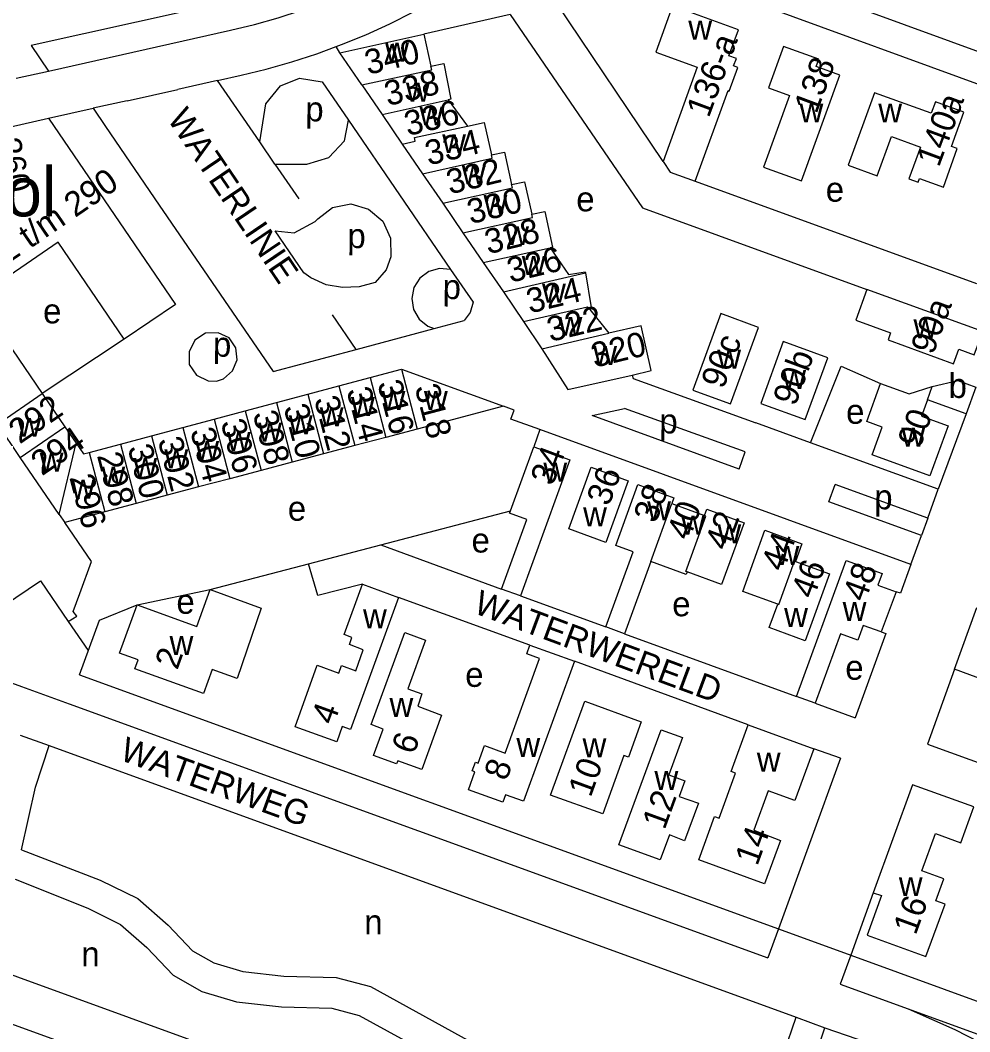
# Model space of a CAD drawing. Extents: x 154320 to 156262, y 382651 to 384180.
# Drawn here: x 155853.4 to 156007.7, y 383033.1 to 383197.4 of the extents above; entities that cross this region are included whole.
import ezdxf

# ---------------------------------------------------------------- set-up
doc = ezdxf.new("R2010")
doc.units = 0
for name, color, linetype in [('BLT_Basislijn', 7, 'Continuous'), ('BLT_Bebouwing', 7, 'Continuous'), ('BLT_Bebouwing_beschrifting', 7, 'Continuous'), ('BLT_Centroide', 7, 'Continuous'), ('BLT_Huisnummer', 7, 'Continuous'), ('BLT_Huisnummer_ tussenligend', 7, 'Continuous'), ('BLT_Huisnummer_reeks', 7, 'Continuous'), ('BLT_Onderverdeling_panden', 7, 'Continuous'), ('BLT_Straatnaam', 7, 'Continuous'), ('BLT_Vlakafsluiter', 7, 'Continuous')]:
    doc.layers.add(name, color=color, linetype=linetype)

msp = doc.modelspace()

# ---------------------------------------------------------------- linework, layer by layer
at = {"layer": 'BLT_Basislijn'}
for p, q in [((155957.88, 383174.46), (155940.61, 383200.09)), ((155933.05, 383198.35), (155919, 383195.11)), ((155855.18, 383193.28), (155858, 383189.14)), ((155905.36, 383192.11), (155904.75, 383193.12)), ((155852.75, 383187.97), (155858, 383189.14)), ((155885.5, 383187.62), (155879.03, 383186.17)), ((155892.33, 383177.64), (155885.5, 383187.62)), ((155870.79, 383184.33), (155865.29, 383183.1)), ((155858.01, 383181.48), (155865.29, 383183.1)), ((155906.77, 383181.19), (155923.36, 383156.92)), ((155894.82, 383174.02), (155892.33, 383177.64)), ((155894.82, 383174.02), (155898.67, 383168.4)), ((155963.09, 383171.24), (156008.81, 383154.64)), ((155899.5, 383156.39), (155894.84, 383163.18)), ((155908.03, 383143.95), (155904.17, 383149.58)), ((155920.68, 383147.32), (155925.56, 383148.62)), ((155908.03, 383143.95), (155920.68, 383147.32)), ((155870.34, 383145.59), (155856.99, 383136.76)), ((155894.54, 383140.36), (155908.03, 383143.95)), ((155946.33, 383133.19), (155951.61, 383134.37)), ((155970.25, 383124.49), (155946.33, 383133.19)), ((155971.22, 383127.33), (155951.61, 383134.37)), ((156007.09, 383133.49), (156002.58, 383121.25)), ((156002.58, 383121.25), (155981.83, 383128.76)), ((155970.25, 383124.49), (155971.22, 383127.33)), ((155984.81, 383119.19), (155985.83, 383122.01)), ((156000.87, 383116.55), (155985.83, 383122.01)), ((156000.87, 383116.55), (156002.58, 383121.25)), ((155999.84, 383113.73), (155984.81, 383119.19)), ((155912.02, 383112.19), (155933.06, 383117.7)), ((156000.87, 383116.55), (155999.84, 383113.73)), ((155998.13, 383109.03), (155999.84, 383113.73)), ((155900.28, 383109.12), (155912.02, 383112.19)), ((155884.29, 383104.93), (155900.28, 383109.12)), ((155872.41, 383102.46), (155884.29, 383104.93)), ((155866.29, 383099.97), (155872.41, 383102.46)), ((155863.08, 383091.1), (155866.29, 383099.97)), ((155861.19, 383099.73), (155864.46, 383095.07)), ((156005.23, 383092.02), (156000.83, 383079.85)), ((155853.42, 383081.31), (155858.12, 383079.6)), ((155858.12, 383079.6), (155979.47, 383035.48)), ((156000.83, 383079.85), (156058.97, 383058.73)), ((155986.69, 383077.55), (155976.61, 383049.82)), ((155992.01, 383055.71), (155988.35, 383045.55)), ((155976.61, 383049.82), (155974.9, 383045.12)), ((155988.35, 383045.55), (155986.65, 383040.85)), ((155979.47, 383035.48), (155984.17, 383033.77))]:
    msp.add_line(p, q, dxfattribs=at)
for points in [[(155932.23, 383223.07), (155925.3, 383217.82), (155914.61, 383210.57), (155899.48, 383204.01), (155880.87, 383198.99), (155855.18, 383193.28)], [(155858, 383189.14), (155887.6, 383195.77), (155891.49, 383196.72), (155895.34, 383197.79), (155899.14, 383199.05), (155902.9, 383200.42), (155906.6, 383201.93), (155910.24, 383203.58), (155913.82, 383205.38), (155918.19, 383207.8), (155924.24, 383211.67), (155929.2, 383214.78)], [(155960.94, 383209.9), (156026.16, 383186.09), (156037.02, 383182.14)], [(156024.45, 383181.39), (155960.61, 383204.7), (155940.61, 383200.09)], [(155904.75, 383193.12), (155905.6, 383193.43), (155909.56, 383195.04), (155913.48, 383196.81), (155917.32, 383198.74), (155920.78, 383200.65)], [(155933.05, 383198.35), (155954.54, 383166.91), (155990.99, 383153.67)], [(155885.5, 383187.62), (155889.31, 383188.47), (155893.38, 383189.46), (155897.53, 383190.62), (155901.61, 383191.96), (155904.75, 383193.12)], [(155892.33, 383177.64), (155893.32, 383183.84), (155895.69, 383186.77), (155898.79, 383187.99), (155902.51, 383187.42), (155906.77, 383181.19)], [(155865.29, 383183.1), (155867.28, 383180.15), (155876.02, 383167.37), (155894.54, 383140.36)], [(155894.82, 383174.02), (155899.97, 383174.02), (155903.57, 383175.08), (155906.09, 383177.8), (155906.77, 383181.19)], [(155894.84, 383163.18), (155897.91, 383162.86), (155901.36, 383164.69), (155901.78, 383165.15), (155904.18, 383166.99), (155907.14, 383167.59), (155910.03, 383166.71), (155912.32, 383164.74), (155913.58, 383162), (155913.66, 383158.98), (155912.87, 383156.86), (155911.1, 383154.81), (155908.49, 383154.09), (155905.78, 383154), (155903.11, 383154.45), (155900.65, 383155.59), (155899.5, 383156.39)], [(155923.36, 383156.92), (155921.56, 383157.09), (155919.82, 383156.59), (155918.37, 383155.51), (155917.35, 383154.01), (155917.07, 383152.22), (155917.34, 383150.43), (155918.24, 383148.86), (155919.65, 383147.73), (155920.68, 383147.32)], [(155923.36, 383156.92), (155926.99, 383151.61), (155926.54, 383149.92), (155925.56, 383148.62)], [(155981.83, 383128.76), (155986.78, 383141.2), (155993.22, 383138.43)], [(155952.86, 383139.78), (155952.99, 383139.19), (155972.93, 383132.03)], [(155937.87, 383130.94), (155933.15, 383132.6), (155933.69, 383134.08), (155931.93, 383134.71)], [(155981.83, 383128.76), (155972.93, 383132.03)], [(155937.87, 383130.94), (155936.86, 383128.14)], [(155998.13, 383109.03), (155937.87, 383130.94)], [(155912.02, 383112.19), (155931.64, 383105.01)], [(155909.06, 383105.8), (155901.79, 383103.97), (155900.28, 383109.12)], [(155998.13, 383109.03), (155996.43, 383104.33), (155995.74, 383104.58)], [(155936.22, 383095.93), (155914.89, 383103.67)], [(155934.69, 383103.9), (155948.55, 383098.88)], [(155830.73, 383097.54), (155853.63, 383089.22)], [(155951.61, 383097.77), (155979.55, 383087.59)], [(155993.32, 383098.05), (155994.05, 383097.79), (155989.08, 383084.12)], [(155971.69, 383082.98), (155943.47, 383093.29)], [(155863.08, 383091.1), (155976.61, 383049.82)], [(155853.63, 383089.22), (155861.38, 383086.4)], [(155861.38, 383086.4), (155974.9, 383045.12)], [(155982.59, 383086.48), (155989.08, 383084.12)], [(155853.65, 383062.66), (155855.93, 383072.86), (155858.12, 383079.6)], [(155986.69, 383077.55), (155982.37, 383079.1)], [(155853.65, 383062.66), (155866.44, 383057.77), (155872.53, 383054.76), (155877.48, 383050.43), (155881.4, 383046.27), (155884.9, 383044.3), (155889.57, 383042.9), (155896.23, 383042.16), (155904.77, 383041.94), (155910.34, 383040.46), (155932.43, 383028.32)], [(155852.58, 383057.9), (155864.43, 383053.19), (155869.73, 383050.56), (155874.01, 383046.82), (155878.28, 383042.3), (155882.92, 383039.67), (155888.57, 383037.98), (155895.89, 383037.17), (155904.05, 383036.95), (155908.47, 383035.79), (155926.08, 383026.11), (155919.49, 383022.53), (155917.44, 383018.56)], [(155903.98, 383015.47), (155817.04, 383047.08)], [(155917.44, 383018.56), (155843.64, 383045.39)], [(155988.35, 383045.55), (156070.59, 383015.65)], [(155986.65, 383040.85), (155997.68, 383036.84)], [(155997.68, 383036.84), (156068.88, 383010.95)], [(155997.68, 383036.84), (156005.3, 383033.52), (156013.2, 383029.41), (156022.56, 383023.53), (156030.91, 383017.21), (156037.92, 383011.01), (156044.25, 383004.31), (156050.51, 382996.85), (156052.83, 382993.58)], [(155932.43, 383028.32), (155941.43, 383024.01), (155958.17, 383023.07), (155962.36, 383025.98), (155967.49, 383028.21), (155972.18, 383028.67), (155975.7, 383027.95), (155976.87, 383028.3), (155977.49, 383029.67), (155979.47, 383035.48)], [(155962.2, 383019.78), (155964.8, 383021.59), (155968.76, 383023.31), (155971.92, 383023.62), (155975.94, 383022.79), (155980.5, 383024.18), (155982.14, 383027.83), (155984.17, 383033.77)], [(155984.17, 383033.77), (155992.84, 383030.77), (156002.07, 383026.75), (156009.47, 383022.9), (156018.29, 383017.36), (156026.15, 383011.4), (156032.7, 383005.62), (156038.64, 382999.33), (156044.57, 382992.26), (156045.87, 382990.43)]]:
    msp.add_lwpolyline(points, dxfattribs=at)
msp.add_lwpolyline([(155886.44, 383139.16), (155887.91, 383140.45), (155888.67, 383142.25), (155888.48, 383144.2), (155887.36, 383145.8), (155885.6, 383146.65), (155883.52, 383146.57), (155881.79, 383145.42), (155880.85, 383143.56), (155880.89, 383141.48), (155882.07, 383139.77), (155883.94, 383138.86), (155885.29, 383138.8)], close=True, dxfattribs=at)
at = {"layer": 'BLT_Bebouwing'}
for p, q in [((155905.36, 383192.11), (155919, 383195.11)), ((155919, 383195.11), (155920.15, 383189.92)), ((155963.42, 383189.75), (155957.88, 383174.46)), ((155908.93, 383186.89), (155912.21, 383182.09)), ((155922.98, 383184.48), (155926.1, 383180.19)), ((155912.21, 383182.09), (155915.5, 383177.29)), ((155821.39, 383173.27), (155858.01, 383181.48)), ((155915.5, 383177.29), (155918.79, 383172.47)), ((155918.79, 383172.47), (155922.07, 383167.67)), ((155922.07, 383167.67), (155925.34, 383162.89)), ((155925.34, 383162.89), (155928.63, 383158.07)), ((155928.63, 383158.07), (155931.92, 383153.27)), ((155931.92, 383153.27), (155935.21, 383148.47)), ((156009.83, 383146.86), (155990.99, 383153.67)), ((155945.76, 383150.67), (155949.08, 383146.58)), ((155935.21, 383148.47), (155938.2, 383144.06)), ((155942.39, 383137.42), (155952.86, 383139.78)), ((156008.68, 383137.82), (156007.09, 383133.49)), ((155959.3, 383118.9), (155964.62, 383116.96)), ((155867.17, 383117.56), (155860.65, 383115.83)), ((155955.89, 383109.5), (155951.61, 383097.77)), ((155856.7, 383106.35), (155861.19, 383099.73)), ((155934.69, 383103.9), (155931.64, 383105.01)), ((156005.23, 383092.02), (156008.87, 383102.02)), ((155861.19, 383099.73), (155862.61, 383100.61)), ((155951.61, 383097.77), (155948.55, 383098.88)), ((155936.22, 383095.93), (155943.47, 383093.29)), ((155982.59, 383086.48), (155979.55, 383087.59)), ((155971.69, 383082.98), (155982.37, 383079.1))]:
    msp.add_line(p, q, dxfattribs=at)
for points in [[(155963.09, 383171.24), (155968.43, 383185.96), (155968.6, 383185.9), (155970.01, 383189.73), (155969.34, 383189.98), (155969.78, 383191.19), (155968.57, 383191.63), (155970.1, 383195.82), (155959.42, 383199.72), (155956.68, 383192.21), (155963.42, 383189.75)], [(155908.93, 383186.89), (155905.36, 383192.11)], [(155977.43, 383193.14), (155974.98, 383186.41), (155978.39, 383185.17), (155974.21, 383173.55), (155980.37, 383171.33), (155986.61, 383188.47), (155982.76, 383189.87), (155983.19, 383191.05), (155977.43, 383193.14)], [(155920.15, 383189.92), (155922.25, 383190.38), (155923.37, 383184.56), (155922.98, 383184.48)], [(155858.01, 383181.48), (155878.66, 383151.25), (155870.34, 383145.59)], [(155926.1, 383180.19), (155928.8, 383180.77), (155929.98, 383175.53)], [(155929.98, 383175.53), (155932.09, 383175.97), (155933.27, 383170.72)], [(155957.88, 383174.46), (155959.05, 383172.72), (155963.09, 383171.24)], [(155933.27, 383170.72), (155935.36, 383171.15), (155936.54, 383165.92)], [(155936.54, 383165.92), (155938.66, 383166.33), (155939.91, 383160.54), (155939.5, 383160.45)], [(155870.34, 383145.59), (155859.58, 383161.33), (155846.37, 383152.3), (155856.99, 383136.76)], [(155939.5, 383160.45), (155942.49, 383156.12), (155945.22, 383156.56), (155945.26, 383156.36)], [(155945.26, 383156.36), (155946.17, 383150.74), (155945.76, 383150.67)], [(155990.99, 383153.67), (155989.19, 383148.68), (155994.83, 383146.63), (155994.42, 383145.49), (156005.07, 383141.61), (156005.93, 383143.96), (156008.44, 383143.06), (156009.83, 383146.86)], [(155952.86, 383139.78), (155955.96, 383140.49), (155954.31, 383147.77), (155949.08, 383146.58)], [(155938.2, 383144.06), (155942.39, 383137.42)], [(155905.21, 383138.03), (155910.29, 383139.38)], [(155910.29, 383139.38), (155915.36, 383140.73)], [(155915.36, 383140.73), (155931.93, 383134.71)], [(155900.14, 383136.68), (155905.21, 383138.03)], [(156000.82, 383135.74), (155999.87, 383133.12), (156004.19, 383131.55), (156001.21, 383123.4), (155991.82, 383126.8), (155993.48, 383131.33), (155990.96, 383132.25), (155993.22, 383138.43)], [(155993.22, 383138.43), (155997.88, 383136.74), (156001.61, 383137.9)], [(156001.61, 383137.9), (156005.74, 383138.89), (156008.68, 383137.82)], [(155856.99, 383136.76), (155860.69, 383131.35)], [(155895.07, 383135.33), (155900.14, 383136.68)], [(155889.99, 383133.98), (155895.07, 383135.33)], [(155931.93, 383134.71), (155917.93, 383131)], [(156007.09, 383133.49), (156000.82, 383135.74)], [(155884.92, 383132.63), (155889.99, 383133.98)], [(155860.69, 383131.35), (155862.5, 383128.7)], [(155874.77, 383129.92), (155879.85, 383131.28)], [(155879.85, 383131.28), (155884.92, 383132.63)], [(155869.7, 383128.57), (155874.77, 383129.92)], [(155912.85, 383129.66), (155907.78, 383128.32)], [(155917.93, 383131), (155912.85, 383129.66)], [(155862.5, 383128.7), (155863.68, 383126.97), (155864.63, 383127.22)], [(155864.63, 383127.22), (155869.7, 383128.57)], [(155907.78, 383128.32), (155902.7, 383126.97)], [(155933.06, 383117.7), (155936.86, 383128.14)], [(155936.86, 383128.14), (155942.73, 383125.99), (155934.69, 383103.9)], [(155821.88, 383106.08), (155833.73, 383114.19), (155833.41, 383114.85), (155831.7, 383117.2), (155831.88, 383117.32), (155828.21, 383122.83), (155833.57, 383126.5), (155837.93, 383120.18), (155838.3, 383120.44), (155850.73, 383102.28), (155856.7, 383106.35)], [(155902.7, 383126.97), (155897.63, 383125.63)], [(155897.63, 383125.63), (155892.55, 383124.28)], [(155946.19, 383124.8), (155952.21, 383122.62), (155948.58, 383112.6), (155942.55, 383114.79), (155946.19, 383124.8)], [(155892.55, 383124.28), (155887.47, 383122.94)], [(155882.4, 383121.6), (155877.32, 383120.25)], [(155887.47, 383122.94), (155882.4, 383121.6)], [(155948.55, 383098.88), (155952.99, 383111.09), (155950.18, 383112.12), (155953.77, 383121.98), (155959.64, 383119.85), (155959.3, 383118.9)], [(155877.32, 383120.25), (155872.25, 383118.91)], [(155872.25, 383118.91), (155867.17, 383117.56)], [(155931.64, 383105.01), (155935.74, 383116.3), (155932.92, 383117.32), (155933.06, 383117.7)], [(155964.62, 383116.96), (155965, 383117.99), (155971.03, 383115.78), (155967.38, 383105.75), (155961.77, 383107.81)], [(155863.11, 383104.3), (155864.98, 383109.5), (155860.65, 383115.83)], [(155976.49, 383102.55), (155970.85, 383104.6), (155974.4, 383114.56), (155980.42, 383112.38), (155979.37, 383109.47)], [(155961.77, 383107.81), (155961.62, 383107.41), (155955.89, 383109.5)], [(155979.37, 383109.47), (155984.93, 383107.47), (155980.98, 383096.64), (155975.12, 383098.78), (155976.49, 383102.55)], [(155979.55, 383087.59), (155987.6, 383109.68), (155993.46, 383107.54), (155992.77, 383105.65), (155995.74, 383104.58)], [(155884.29, 383104.93), (155892.59, 383101.93), (155888.7, 383090.49), (155884.62, 383091.97), (155883.21, 383088.04), (155872.02, 383092.09), (155872.57, 383093.53), (155869.55, 383094.61), (155872.41, 383102.46)], [(155872.41, 383102.46), (155882.12, 383098.94), (155884.29, 383104.93)], [(155914.89, 383103.67), (155907.09, 383082.19), (155905.75, 383082.68), (155904.85, 383080.2), (155898.08, 383082.65), (155901.69, 383092.64), (155905.2, 383091.37), (155905.64, 383092.59), (155907.97, 383091.75), (155909.16, 383095.16), (155906.9, 383096.02), (155907.31, 383097.17), (155906.08, 383097.62), (155909.06, 383105.8)], [(155909.06, 383105.8), (155914.89, 383103.67)], [(155862.61, 383100.61), (155862.03, 383101.35), (155863.11, 383104.3)], [(155995.74, 383104.58), (155993.32, 383098.05)], [(156008.87, 383102.02), (156014.88, 383099.83), (156011.22, 383089.81), (156005.23, 383092.02)], [(155993.32, 383098.05), (155990.4, 383099.13), (155989.52, 383096.72), (155986.71, 383097.75), (155982.59, 383086.48)], [(155943.47, 383093.29), (155935.2, 383070.57), (155932.27, 383071.63), (155931.82, 383070.39), (155926.24, 383072.42), (155927.29, 383075.33), (155926.87, 383075.48), (155927.38, 383076.89), (155927.81, 383076.74), (155928.85, 383079.61), (155932.24, 383078.38), (155937.82, 383093.75), (155935.71, 383094.52), (155936.22, 383095.93)], [(155982.37, 383079.1), (155979.28, 383070.68), (155974.95, 383072.27), (155972.6, 383065.84), (155976.93, 383064.21), (155974.35, 383057.15), (155963.67, 383061.05), (155966.25, 383068.1), (155966.96, 383067.84), (155969.65, 383075.14), (155968.92, 383075.41), (155971.69, 383082.98)], [(156008.37, 383069.63), (155998.4, 383073.25), (155992.01, 383055.71)], [(155992.01, 383055.71), (155993.34, 383055.23), (155991.01, 383048.81), (156000.58, 383045.34), (156003.68, 383053.86), (156002.17, 383054.41), (156003.47, 383057.94), (155999.89, 383059.25), (156002.11, 383065.33), (156006.26, 383063.82), (156008.37, 383069.63)]]:
    msp.add_lwpolyline(points, dxfattribs=at)
for points in [[(156006.76, 383182.49), (156002.14, 383184.17), (156001.45, 383182.28), (155992.24, 383185.63), (155987.96, 383173.84), (155992.65, 383172.12), (155994.97, 383178.52), (155999.69, 383176.81), (155997.81, 383171.64), (155999.31, 383171.08), (155999.55, 383171.69), (156003.43, 383170.28), (156005.67, 383176.56), (156004.73, 383176.91)], [(155967.27, 383149.76), (155962.72, 383137.34), (155968.84, 383135.09), (155973.4, 383147.51)], [(155977.4, 383145.23), (155973.77, 383135.18), (155980.98, 383132.54), (155984.65, 383142.58)], [(155915.89, 383097.95), (155919.29, 383096.7), (155916.4, 383088.82), (155918.7, 383087.98), (155918, 383086.01), (155921.89, 383084.54), (155918.68, 383075.71), (155914.75, 383077.13), (155914.56, 383076.63), (155910.85, 383077.98), (155912.41, 383082.29), (155910.43, 383083.01)], [(155945.14, 383086.8), (155954.33, 383083.47), (155952.24, 383077.7), (155951.49, 383077.97), (155948.07, 383068.54), (155939.6, 383071.53)], [(155957.56, 383082.18), (155961.05, 383080.9), (155958.83, 383074.83), (155961.4, 383073.89), (155960.46, 383071.35), (155963.62, 383070.25), (155961.36, 383064.15), (155958.9, 383065.09), (155957.41, 383061.07), (155950.71, 383063.51)]]:
    msp.add_lwpolyline(points, close=True, dxfattribs=at)
at = {"layer": 'BLT_Onderverdeling_panden'}
for p, q in [((155908.93, 383186.89), (155920.28, 383189.36)), ((155920.28, 383189.36), (155920.15, 383189.92)), ((155912.21, 383182.09), (155922.98, 383184.48)), ((155930.09, 383175.01), (155929.98, 383175.53)), ((155918.79, 383172.47), (155930.09, 383175.01)), ((155933.39, 383170.17), (155933.27, 383170.72)), ((155922.07, 383167.67), (155933.39, 383170.17)), ((155928.63, 383158.07), (155939.5, 383160.45)), ((155931.92, 383153.27), (155945.26, 383156.36)), ((155938.2, 383144.06), (155949.08, 383146.58)), ((155910.29, 383139.38), (155912.85, 383129.66)), ((155915.36, 383140.73), (155917.93, 383131)), ((155905.21, 383138.03), (155907.78, 383128.32)), ((156000.82, 383135.74), (156001.61, 383137.9)), ((155849.74, 383131.79), (155856.99, 383136.76)), ((155900.14, 383136.68), (155902.7, 383126.97)), ((155895.07, 383135.33), (155897.63, 383125.63)), ((155889.99, 383133.98), (155892.55, 383124.28)), ((155853.43, 383126.39), (155849.74, 383131.79)), ((155853.43, 383126.39), (155860.69, 383131.35)), ((155879.85, 383131.28), (155882.4, 383121.6)), ((155884.92, 383132.63), (155887.47, 383122.94)), ((155874.77, 383129.92), (155877.32, 383120.25)), ((155859.77, 383117.12), (155862.5, 383128.7)), ((155869.7, 383128.57), (155872.25, 383118.91)), ((155859.77, 383117.12), (155853.43, 383126.39)), ((155864.63, 383127.22), (155867.17, 383117.56)), ((155955.89, 383109.5), (155959.3, 383118.9)), ((155859.77, 383117.12), (155860.65, 383115.83))]:
    msp.add_line(p, q, dxfattribs=at)
for points in [[(155915.5, 383177.29), (155917.6, 383177.75), (155917.46, 383178.35), (155926.1, 383180.19)], [(155925.34, 383162.89), (155936.66, 383165.38), (155936.54, 383165.92)], [(155935.21, 383148.47), (155945.6, 383150.86), (155945.76, 383150.67)], [(155961.77, 383107.81), (155961.55, 383107.88), (155964.84, 383116.88), (155964.62, 383116.96)], [(155976.49, 383102.55), (155976.66, 383102.49), (155979.21, 383109.53), (155979.37, 383109.47)]]:
    msp.add_lwpolyline(points, dxfattribs=at)
at = {"layer": 'BLT_Vlakafsluiter'}
for p, q in [((155870.79, 383184.33), (155879.03, 383186.17)), ((155976.61, 383049.82), (155988.35, 383045.55))]:
    msp.add_line(p, q, dxfattribs=at)

# ---------------------------------------------------------------- texts
at = {"layer": 'BLT_Bebouwing_beschrifting'}
msp.add_text('School', height=8, dxfattribs=at).set_placement((155826.62, 383165.55))
at = {"layer": 'BLT_Centroide'}
for s, p in [('w', (155961.97, 383194.25)), ('w', (155912.71, 383190.68)), ('w', (155916.1, 383184.16)), ('w', (155980.04, 383180.79)), ('w', (155992.84, 383180.79)), ('w', (155918.29, 383180.31)), ('w', (155921.98, 383175.82)), ('w', (155925.17, 383170.74)), ('e', (155984.3, 383167.93)), ('w', (155928.7, 383165.95)), ('e', (155943.77, 383166.36)), ('w', (155932.23, 383160.88)), ('w', (155934.91, 383156.04)), ('w', (155938.21, 383151.54)), ('e', (155857.14, 383148.17)), ('w', (155940.9, 383146.15)), ('w', (155998.56, 383145.74)), ('w', (155946.53, 383141.42)), ('w', (155966.67, 383140.81)), ('w', (155977.24, 383137.52)), ('b', (156004.26, 383136.06)), ('w', (155907.17, 383133.13)), ('w', (155912.13, 383134.09)), ('w', (155919.02, 383134.09)), ('w', (155902.09, 383131.44)), ('e', (155987.61, 383131.86)), ('w', (155852.97, 383129.75)), ('w', (155897.06, 383130.14)), ('w', (155892.08, 383128.98)), ('w', (155996.58, 383128.15)), ('w', (155887, 383127.46)), ('w', (155881.87, 383125.99)), ('w', (155856.59, 383124.08)), ('w', (155871.81, 383123.24)), ('w', (155876.85, 383124.63)), ('w', (155866.62, 383121.85)), ('w', (155938.42, 383122.47)), ('w', (155861.71, 383119.69)), ('e', (155896.9, 383116.12)), ('w', (155944.88, 383115.21)), ('w', (155955.28, 383116.19)), ('w', (155960.81, 383113.86)), ('w', (155966.7, 383112.47)), ('e', (155926.75, 383110.95)), ('w', (155976.14, 383108.95)), ('e', (155878.8, 383101.01)), ('e', (155959.36, 383100.6)), ('w', (155909.12, 383098.65)), ('w', (155977.54, 383098.85)), ('w', (155987.05, 383099.84)), ('w', (155877.69, 383094.3)), ('e', (155987.48, 383090.29)), ('e', (155925.73, 383089.14)), ('w', (155913.42, 383084.27)), ('w', (155934.04, 383077.77)), ('w', (155944.79, 383077.7)), ('w', (155973.1, 383075.39)), ('w', (155956.47, 383072.38)), ('w', (155996.17, 383055.16)), ('n', (155909.32, 383048.95)), ('n', (155863.35, 383043.75))]:
    msp.add_text(s, height=4, dxfattribs=at).set_placement(p)
for p in [(155899.73, 383180.99), (155906.57, 383160.41), (155922.04, 383152.12), (155884.73, 383142.77), (155957.25, 383130.31), (155992.17, 383117.99)]:
    msp.add_text('p', height=4, rotation=359.5, dxfattribs=at).set_placement(p)
at = {"layer": 'BLT_Huisnummer'}
for s, rotation, p in [('340', 13.5777, (155909.93, 383188.51)), ('138', 69.5777, (155982.79, 383182.06)), ('336', 13.5777, (155916.37, 383178.57)), ('140a', 69.5777, (156002.68, 383173.4)), ('332', 13.5777, (155923.21, 383169.09)), ('328', 13.5777, (155929.43, 383159.37)), ('324', 13.5777, (155936.2, 383149.76)), ('90a', 69.5777, (156001.74, 383142.92)), ('320', 13.5777, (155946.73, 383140.95)), ('90c', 69.5777, (155967.67, 383137.35)), ('90b', 69.5777, (155979.34, 383134.58)), ('316', 284.7819, (155911.42, 383138.44)), ('318', 284.7819, (155917.49, 383137.78)), ('292', 34.361, (155853.33, 383128.48)), ('312', 284.7819, (155901.15, 383135.85)), ('308', 284.7819, (155891.19, 383133.49)), ('90', 69.5777, (155999.6, 383127.73)), ('304', 284.7819, (155881.02, 383130.72)), ('300', 284.7819, (155870.85, 383128)), ('34', 69.5774, (155939.94, 383121.64)), ('296', 284.7819, (155861.38, 383123.17)), ('38', 69.5774, (155956.69, 383115.56)), ('42', 69.5774, (155968.29, 383111.1)), ('48', 69.5774, (155990.68, 383102.76)), ('2', 70.0188, (155878.95, 383091.76)), ('4', 70.0188, (155904.34, 383082.81)), ('6', 70.0188, (155917.39, 383078)), ('8', 70.0175, (155932.42, 383073.72)), ('10', 70.0192, (155946.1, 383071.06)), ('12', 70.0191, (155958.12, 383065.8)), ('14', 70.0186, (155973.18, 383059.93)), ('16', 70.0191, (155998.91, 383048.69))]:
    msp.add_text(s, height=4, rotation=rotation, dxfattribs=at).set_placement(p)
at = {"layer": 'BLT_Huisnummer_ tussenligend'}
for s, rotation, p in [('338', 13.5777, (155913.13, 383183.44)), ('334', 13.5777, (155919.75, 383173.79)), ('330', 13.5777, (155926.58, 383164.26)), ('326', 13.5777, (155933.06, 383154.75)), ('322', 13.5777, (155939.55, 383145.14)), ('314', 284.7819, (155906.41, 383137.29)), ('310', 284.7819, (155896.19, 383134.54)), ('294', 34.361, (155856.94, 383123.31)), ('306', 284.7819, (155885.97, 383132.1)), ('302', 284.7819, (155875.75, 383129.21)), ('298', 284.7819, (155865.87, 383126.72)), ('36', 69.5774, (155949.07, 383118.34)), ('40', 69.5774, (155962.1, 383112.78)), ('44', 69.5774, (155977.42, 383107.69)), ('46', 69.5774, (155982.29, 383103.27))]:
    msp.add_text(s, height=4, rotation=rotation, dxfattribs=at).set_placement(p)
at = {"layer": 'BLT_Huisnummer_reeks'}
for s, rotation, p in [('136-a', 69.5777, (155965.29, 383181.42)), ('260', 282.645, (155849.46, 383177.84)), ('272 t/m 290', 34.361, (155846.38, 383154.36))]:
    msp.add_text(s, height=4, rotation=rotation, dxfattribs=at).set_placement(p)
at = {"layer": 'BLT_Straatnaam'}
for s, rotation, p in [('WATERLINIE', 304.0883, (155877.21, 383181.37)), ('WATERWERELD', 339.5777, (155926.88, 383101.2)), ('WATERWEG', 339.9786, (155869.39, 383077.34))]:
    msp.add_text(s, height=4, rotation=rotation, dxfattribs=at).set_placement(p)

doc.saveas('drawing.dxf')
